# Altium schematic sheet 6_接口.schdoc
size 309 x 223 mm; Symbol: Sheet-Symbol_A4; Device: Sheet-Symbol_A4; Company: 嘉立创EDA; Version: V1.0; Page Size: A4; @Project Name: 共享电动车中控; @Page Count: 11; @Update Date: 2024-11-20; @Create Date: 2024-09-26; @Schematic Name: SCH; @Page No: 6; @Page Name: 接口; @Board Name: STM32F103C8T6; @Create Time: 02:39:01; @Update Time: 00:12:19
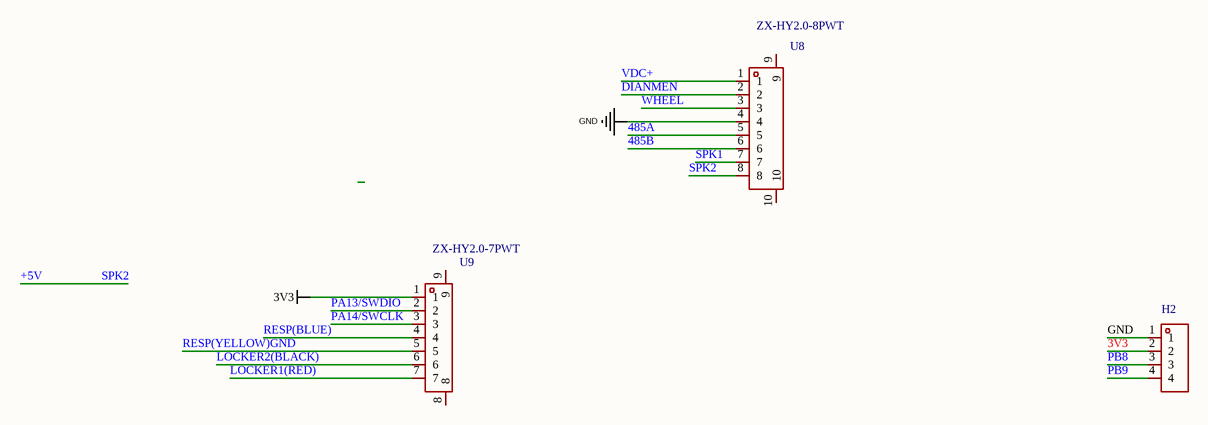
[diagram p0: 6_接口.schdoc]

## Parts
H2  HDR-M_2.54_1x4P  [HDR-TH_4P-P2.54-V-M]  (value not drawn)
U8  ZX-HY2.0-8PWT  [CONN-SMD_8P-P2.00_WAFER-HY2.0-8PWB]  (value not drawn)
U9  ZX-HY2.0-7PWT  [CONN-SMD_7P-P2.00_ZX-HY2.0-7PWT]  (value not drawn)

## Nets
3V3: H2.2 U9.1
GND: H2.1 U8.4
485A: U8.5
485B: U8.6
+5V: U8.8  [also labelled SPK2]
DIANMEN: U8.2
LOCKER1(RED): U9.7
LOCKER2(BLACK): U9.6
PA13/SWDIO: U9.2
PA14/SWCLK: U9.3
PB8: H2.3
PB9: H2.4
RESP(BLUE): U9.4
RESP(YELLOW)GND: U9.5
SPK1: U8.7
VDC+: U8.1
WHEEL: U8.3

Not connected (* = marked no-connect by the designer): U8 9 10; U9 8 9

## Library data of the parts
H2 = HDR-M_2.54_1x4P: Symbol: PZ254V-11-04P; Convert to PCB: yes
U8 = ZX-HY2.0-8PWT: 插针结构:1x8P;间距:2mm;安装方式:卧贴;参考系列:HY;总PIN数:8P;排数:1;每排PIN数:8;行距:-;额定电流:2A;触头材质:黄铜;触头镀层:锡;工作温度范围:-25℃~+85℃;; Manufacturer: Megastar(兆星); Add into BOM: yes; Pins Structure: 1x8P; Pitch: 2mm; Reference Series: HY; Number of PINs Per Row: 8; Current Rating (Max): 2A
U9 = ZX-HY2.0-7PWT: 插针结构:1x7P;间距:2mm;安装方式:卧贴;参考系列:HY;总PIN数:7P;排数:1;每排PIN数:7;行距:-;额定电流:2A;触头材质:黄铜;触头镀层:锡;工作温度范围:-25℃~+85℃;; Manufacturer: Megastar(兆星); Add into BOM: yes; Pins Structure: 1x7P; Pitch: 2mm; Reference Series: HY; Number of PINs Per Row: 7; Current Rating (Max): 2A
